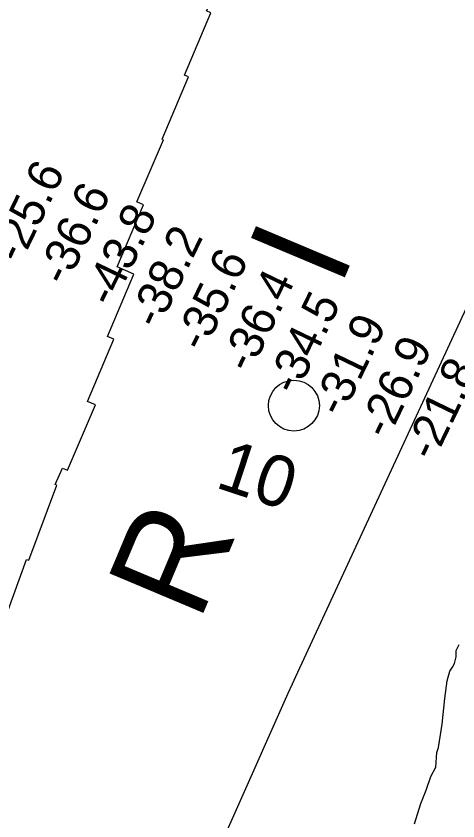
# Model space of a CAD drawing. Extents: x 3148686 to 3186545, y 916144 to 941516.
# Drawn here: x 3159855 to 3160723, y 928865 to 930448 of the extents above; entities that cross this region are included whole.
import ezdxf

# ---------------------------------------------------------------- set-up
doc = ezdxf.new("R2010")
doc.units = 0
for name, color, linetype in [('V-RIVR-EDGE', 7, 'Continuous'), ('V-RIVR-IDEN', 7, 'Continuous'), ('V-RIVR-MILE', 7, 'Continuous'), ('V-RIVR-RANG', 7, 'Continuous'), ('V-RRAP-RVMT', 7, 'Continuous'), ('V-TOPO-BNDY', 7, 'Continuous')]:
    doc.layers.add(name, color=color, linetype=linetype)

msp = doc.modelspace()

# ---------------------------------------------------------------- linework, layer by layer
at = {"layer": 'V-RIVR-EDGE'}
for points in [[(3160707.3, 929159.5), (3160712.8, 929167.1), (3160716.7, 929174.4), (3160719.8, 929187.5), (3160719.8, 929200), (3160725.4, 929211.9)], [(3160638, 928859.4), (3160650.3, 928899.3), (3160660.7, 928925.7), (3160669.9, 928952.2), (3160680, 928971.1), (3160681.9, 928999.4), (3160684.7, 929009.7), (3160692.4, 929055.4), (3160697.4, 929105.7), (3160702, 929140.4), (3160707.3, 929159.5)]]:
    msp.add_lwpolyline(points, dxfattribs=at)
at = {"layer": 'V-RIVR-MILE'}
msp.add_circle((3160400.9, 929681.8), 50, dxfattribs=at)
at = {"layer": 'V-RRAP-RVMT'}
for points in [[(3159946.2, 929558.8), (3159956.2, 929554.6), (3160010.9, 929683.4), (3159995.4, 929690), (3160047.4, 929812.4), (3160034.8, 929817.8), (3160086.8, 929940.2), (3160053.6, 929954.4), (3160105.6, 930076.7), (3160092.6, 930082.3), (3160144.6, 930204.6), (3160142.1, 930205.7), (3160194, 930328.1), (3160185.7, 930331.7), (3160237.7, 930454.1), (3160229, 930457.8), (3160278.7, 930555.6), (3160260.3, 930565), (3160320.7, 930683.4), (3160265.6, 930711.5)], [(3159826.1, 929241.7), (3159875.8, 929379.4), (3159880.5, 929377.6), (3159935.5, 929525), (3159931.9, 929526.8), (3159946.2, 929558.8)]]:
    msp.add_lwpolyline(points, dxfattribs=at)
at = {"layer": 'V-TOPO-BNDY'}
msp.add_lwpolyline([(3159006.2, 926311.1), (3159280.9, 926819.7), (3159355.2, 926960.9), (3159433.9, 927110.7), (3159462.3, 927164.6), (3160176.1, 928635), (3160389.8, 929116.4), (3160397.9, 929134.5), (3160404.6, 929149.2), (3160858.7, 930130.4), (3161037.6, 930526.5), (3161154.7, 930785.7), (3161271.9, 931050.2), (3161316.1, 931173.6), (3161356.8, 931287.5), (3161429, 931551), (3161684.4, 932501.7), (3161786.7, 932820.9), (3161812.5, 932901.9), (3162033.7, 933562.9)], dxfattribs=at)

# ---------------------------------------------------------------- texts
at = {"layer": 'V-RIVR-IDEN'}
for s, height, rotation, p in [('R       I', 200, 67.161, (3160214.6, 929253.9)), ('10', 100, 341.7937, (3160244.1, 929521.6))]:
    msp.add_text(s, height=height, rotation=rotation, dxfattribs=at).set_placement(p)
at = {"layer": 'V-RIVR-RANG'}
for s, p in [('-25.6', (3159863.4, 929957.7)), ('-36.6', (3159953.6, 929914.4)), ('-43.8', (3160044.5, 929872.8)), ('-38.2', (3160134.7, 929829.6)), ('-35.6', (3160224, 929784.6)), ('-36.4', (3160315, 929743)), ('-34.5', (3160405.2, 929699.8)), ('-31.9', (3160495.2, 929656.3)), ('-26.9', (3160585.3, 929613)), ('-21.8', (3160675.6, 929570))]:
    msp.add_text(s, height=67, rotation=64.2183, dxfattribs=at).set_placement(p)

doc.saveas('drawing.dxf')
